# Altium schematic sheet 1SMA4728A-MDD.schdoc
size 127 x 101 mm
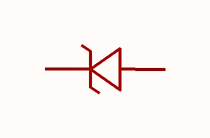
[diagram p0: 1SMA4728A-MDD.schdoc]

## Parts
D?  1sma4728a_c523836  [SMA_L4.3-W2.6-LS5.0-RD]  (value not drawn)

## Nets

Not connected (* = marked no-connect by the designer): D? 1(K) 2(A)

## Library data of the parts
D? = 1sma4728a_c523836: 二极管配置:1个独立式;稳压值(标称值):3.3V;稳压值(范围值):3.1V~3.5V;耗散功率(Pd):1W;; Manufacturer: MDD(辰达半导体); AddInBom: yes; SymbolName: 1SMA4728A-MDD; ModelId: 8d2dd2e50a3a4b27821fa63d469a8f11; ModelTransform: 196.85,102.362,0,0,0,0,0,0,0; Diode Configuration: 1个独立式; Zener Voltage(Nom): 3.3V; Reverse Leakage Current (Ir): 100uA@1V; Pd - Power Dissipation: 1W; Impedance(Zzt): 10Ω; Operating Junction Temperature Range: -55℃~+150℃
